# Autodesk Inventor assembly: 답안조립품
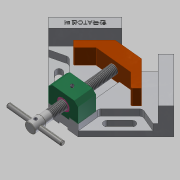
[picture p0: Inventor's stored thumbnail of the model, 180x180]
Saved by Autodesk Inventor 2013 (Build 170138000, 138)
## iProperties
Created: 2019-04
Part Number: 답안조립품
Document SubType Name: Assembly
Designer: Administrator
Author: Administrator
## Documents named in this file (11)
- C:\Users\Administrator\Desktop\490407V1015\답안조립품.iam
- C:\Users\Administrator\Desktop\490407V1015\베이스.ipt
- C:\Users\Administrator\Desktop\490407V1015\리드스크류.ipt
- C:\Users\Administrator\Desktop\490407V1015\멈춤나사 M4x5.ipt
- C:\Users\Administrator\Desktop\490407V1015\멈춤나사 M4x10.ipt
- C:\Users\Administrator\Desktop\490407V1015\볼트 M4x16.ipt
- C:\Users\Administrator\Desktop\490407V1015\부시.ipt
- C:\Users\Administrator\Desktop\490407V1015\서포트.ipt
- C:\Users\Administrator\Desktop\490407V1015\조.ipt
- C:\Users\Administrator\Desktop\490407V1015\평행 핀 2.5x24.ipt
- C:\Users\Administrator\Desktop\490407V1015\핸들.ipt
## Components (1 placed, 1 different names)
1. 핸들:1
